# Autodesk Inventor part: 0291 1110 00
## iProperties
Shininess: 25.0
Length Units: 11269
Angle Units: 11279
Time Units: 11290
Mass Units: 11283
Length Display Precision: 3
Angle Display Precision: 2
Compacted: True
Created: 2001-01
Part Number: 0291 1110 00
Material: Steel, Mild
Document SubType Name: Modeling
Designer: Joe M
Description: Nut
Engineer: Joe M
Density: 0.0
Volumn: 0.0
Area: 0.0
PropertySet Name: Model Information
Control State: 0
Master: False
Checked Out: False
Last Check In Date: 2001-01-31
Last Check In By: iujhd
Title: Mutter
Author: Joe M
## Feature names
1. Extrusion1
2. Base1
